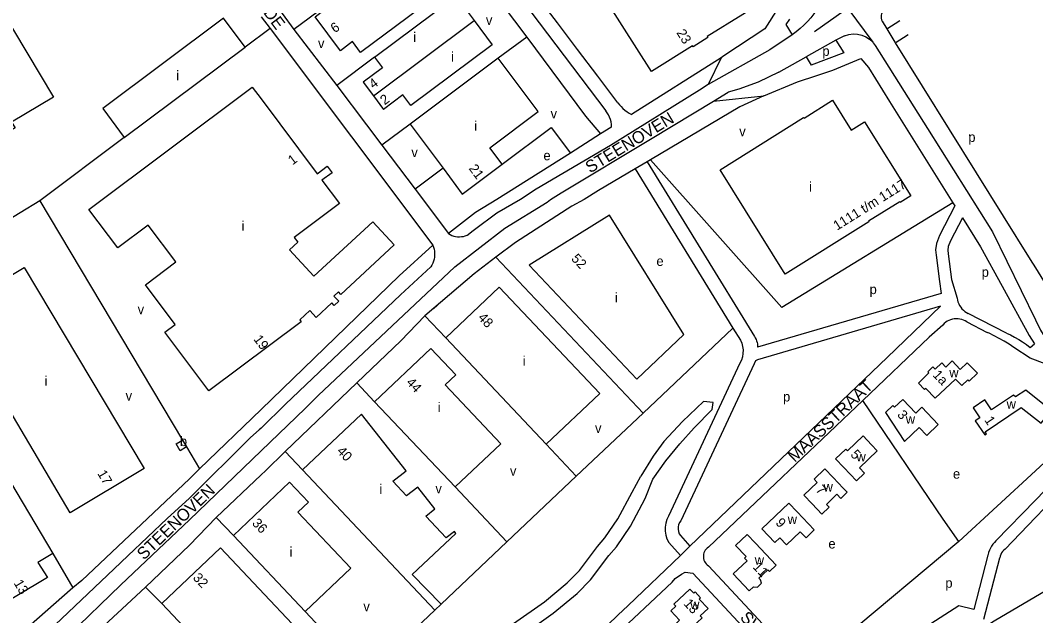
# Model space of a CAD drawing. Extents: x 156721 to 158827, y 386657 to 388950.
# Drawn here: x 157630 to 158050.1, y 388328 to 388574.1 of the extents above; entities that cross this region are included whole.
import ezdxf

# ---------------------------------------------------------------- set-up
doc = ezdxf.new("R2010")
doc.units = 0
for name, color, linetype in [('BLT_Basislijn', 7, 'Continuous'), ('BLT_Bebouwing', 7, 'Continuous'), ('BLT_Centroide', 7, 'Continuous'), ('BLT_Huisnummer', 7, 'Continuous'), ('BLT_Huisnummer_reeks', 7, 'Continuous'), ('BLT_Onderverdeling_panden', 7, 'Continuous'), ('BLT_Straatnaam', 7, 'Continuous'), ('BLT_Vlakafsluiter', 7, 'Continuous')]:
    doc.layers.add(name, color=color, linetype=linetype)

msp = doc.modelspace()

# ---------------------------------------------------------------- linework, layer by layer
at = {"layer": 'BLT_Basislijn'}
for p, q in [((157729.65, 388588.92), (157743.2, 388570.34)), ((157756.41, 388580.15), (157743.2, 388570.34)), ((157729.65, 388575.61), (157733.33, 388570.72)), ((157943.56, 388579.24), (157938.08, 388570.62)), ((157970.91, 388578.09), (157958.64, 388569.41)), ((157948.27, 388574.59), (157946.73, 388572.37)), ((157946.73, 388572.37), (157949.36, 388568.15)), ((157986.64, 388573.72), (157988.5, 388570.64)), ((157988.5, 388570.64), (157993.92, 388574.08)), ((157733.33, 388570.72), (157723.08, 388563.03)), ((157733.33, 388570.72), (157800.68, 388481.2)), ((157743.2, 388570.34), (157761.02, 388547.23)), ((157839.52, 388567.15), (157827.78, 388558.41)), ((157949.36, 388568.15), (157940.12, 388561.92)), ((157971.04, 388567.72), (157967.45, 388565.88)), ((157988.5, 388570.64), (157991.84, 388565.12)), ((157992, 388564.86), (157997.39, 388568.26)), ((157967.45, 388565.88), (157955.08, 388558.95)), ((157967.45, 388565.88), (157970.66, 388560.71)), ((157983.67, 388563.72), (158005.28, 388529.41)), ((157991.84, 388565.12), (157992, 388564.86)), ((157992, 388564.86), (158047.87, 388475.3)), ((157776.63, 388558.9), (157761.02, 388547.23)), ((157940.12, 388561.92), (157914.59, 388547.57)), ((157943.81, 388552.66), (157955.08, 388558.95)), ((157955.08, 388558.95), (157957.22, 388555.52)), ((157970.66, 388560.71), (157957.22, 388555.52)), ((157919.92, 388558.64), (157882.88, 388535.23)), ((157919.92, 388558.64), (157914.59, 388547.57)), ((157966.24, 388553.56), (157977.83, 388558.37)), ((157977.83, 388558.37), (157980.87, 388554.56)), ((157980.87, 388554.56), (157989.62, 388540.54)), ((157943.81, 388552.66), (157935.31, 388548.5)), ((157951.6, 388548.73), (157959.49, 388551.33)), ((157959.49, 388551.33), (157966.24, 388553.56)), ((157761.02, 388547.23), (157773.25, 388530.97)), ((157935.31, 388548.5), (157927.29, 388545.62)), ((157937.66, 388542.9), (157951.6, 388548.73)), ((157916.83, 388540.74), (157937.66, 388542.9)), ((157927.29, 388545.62), (157922.85, 388544.41)), ((157989.62, 388540.54), (158015.89, 388498.67)), ((157773.25, 388530.97), (157779.65, 388522.46)), ((157791.32, 388531.17), (157779.65, 388522.46)), ((157874.37, 388529.85), (157870.11, 388527.16)), ((157874.67, 388530.04), (157874.37, 388529.85)), ((157673.06, 388525.66), (157638.1, 388499.53)), ((157779.65, 388522.46), (157793.34, 388504.27)), ((157804.94, 388512.94), (157793.34, 388504.27)), ((157889.4, 388515.68), (157884.38, 388512.71)), ((157890.71, 388516.46), (157889.4, 388515.68)), ((157890.71, 388516.46), (157945.1, 388455.4)), ((157793.34, 388504.27), (157807.12, 388485.95)), ((157638.1, 388499.53), (157697.08, 388400.6)), ((158015.89, 388498.67), (157945.1, 388455.4)), ((158016.7, 388497.38), (158010.32, 388485.12)), ((158015.89, 388498.67), (158016.7, 388497.38)), ((158019.79, 388492.48), (158014.86, 388483.01)), ((158019.79, 388492.48), (158027.33, 388480.51)), ((158010.32, 388485.12), (158009.01, 388481.93)), ((157800.68, 388481.2), (157786.7, 388468.5)), ((158009.01, 388481.93), (158008.69, 388479.25)), ((158008.69, 388479.25), (158008.89, 388477.03)), ((158013.9, 388480.66), (158013.72, 388479.17)), ((158013.72, 388479.17), (158013.86, 388477.57)), ((158014.86, 388483.01), (158013.9, 388480.66)), ((158027.33, 388480.51), (158036.28, 388464.18)), ((157826.79, 388476.17), (157887.67, 388411.8)), ((158008.89, 388477.03), (158010.28, 388466.17)), ((158013.86, 388477.57), (158015.21, 388467.02)), ((158047.87, 388475.3), (158050, 388471.85)), ((157786.7, 388468.5), (157729.65, 388413.31)), ((158015.21, 388467.02), (158017.56, 388459.27)), ((158010.28, 388466.17), (158011.03, 388461.21)), ((158036.28, 388464.18), (158047.43, 388443.84)), ((158011.03, 388461.21), (157935.06, 388439.02)), ((157800.99, 388454.87), (157802.57, 388456.33)), ((158010.76, 388455.93), (157935.08, 388433.82)), ((157988.68, 388434.81), (158010.76, 388455.93)), ((157797.44, 388451.9), (157806.01, 388442.84)), ((158037.96, 388444.87), (158022.19, 388452.96)), ((157924.81, 388446.92), (157927.94, 388441.94)), ((158011.66, 388448.17), (158006.07, 388443.14)), ((158021.61, 388449.47), (158030.04, 388445.14)), ((158006.07, 388443.14), (157978.63, 388416.92)), ((158047.43, 388443.84), (158049.65, 388440.39)), ((158047.83, 388434.46), (158041.01, 388438.89)), ((158047.79, 388438.91), (158049.65, 388440.39)), ((157988.68, 388434.81), (157907.08, 388356.74)), ((157934.18, 388433.31), (157933.6, 388432.15)), ((157935.08, 388433.82), (157934.18, 388433.31)), ((158054.07, 388432.16), (158047.83, 388434.46)), ((157927.74, 388432.4), (157898.21, 388369.17)), ((157933.6, 388432.15), (157903.25, 388367.25)), ((157912.61, 388416.54), (157904.05, 388408.36)), ((157916.61, 388416.15), (157912.61, 388416.54)), ((157914.69, 388356.3), (157978.63, 388416.92)), ((157916.22, 388413.23), (157916.61, 388416.15)), ((157729.65, 388413.31), (157704.2, 388388.68)), ((157908.82, 388405.63), (157916.22, 388413.23)), ((157904.05, 388408.36), (157896.26, 388400.08)), ((157902.88, 388399.11), (157908.82, 388405.63)), ((157896.26, 388400.08), (157891.78, 388393.95)), ((157897.13, 388392.1), (157902.88, 388399.11)), ((157698.78, 388397.76), (157704.2, 388388.68)), ((157746.83, 388388.26), (157739.66, 388395.84)), ((157847.61, 388398.86), (157860.06, 388385.69)), ((157891.78, 388393.95), (157886.81, 388385.74)), ((157891.76, 388384.48), (157897.13, 388392.1)), ((157729.65, 388386.26), (157731.4, 388387.92)), ((158018.35, 388358.76), (158050, 388387.9)), ((158053.89, 388379.75), (158050, 388375.75)), ((158050, 388375.75), (158033.66, 388358.95)), ((158050, 388368.56), (158057.52, 388376.31)), ((157711.07, 388368.58), (157718.17, 388361.13)), ((158037.41, 388355.59), (158050, 388368.56)), ((157898.28, 388358.34), (157903.11, 388352.94)), ((157903.15, 388361.15), (157907.08, 388356.74)), ((158018.35, 388358.76), (157954.86, 388305.75)), ((158050, 388335.95), (158090.42, 388359.89)), ((157643.55, 388353.78), (157651.82, 388339.53)), ((157903.11, 388352.94), (157881.5, 388332.26)), ((157907.08, 388356.74), (157903.11, 388352.94)), ((158030.32, 388353.03), (158024.57, 388330.64)), ((157954.86, 388305.75), (157914.69, 388348.69)), ((158028.62, 388326.61), (158035.21, 388351.98)), ((157899.76, 388341.9), (157854.79, 388299.87)), ((157651.82, 388339.54), (157630.02, 388320.43)), ((157653.95, 388314.01), (157681.86, 388339.8)), ((157681.86, 388339.8), (157688.52, 388333.06)), ((157877.17, 388328.3), (157881.5, 388332.26)), ((157747.91, 388329.81), (157772.88, 388303.23))]:
    msp.add_line(p, q, dxfattribs=at)
for points in [[(157817.1, 388609.55), (157872.27, 388536.72)], [(157877.21, 388540.06), (157868.9, 388551.04), (157860.59, 388562.02), (157852.28, 388573), (157843.97, 388583.98), (157836.41, 388593.96)], [(157820.95, 388592), (157834.44, 388573.94)], [(157986.64, 388573.72), (157986.45, 388574.32), (157986.33, 388574.94), (157986.3, 388575.57), (157986.34, 388576.19), (157986.46, 388576.81), (157986.67, 388577.41), (157986.94, 388577.97), (157987.29, 388578.5), (157987.69, 388578.98), (157988.16, 388579.41), (157988.67, 388579.77), (157989.23, 388580.06), (157989.82, 388580.28), (157990.17, 388580.36)], [(157959.58, 388578.52), (157958.38, 388576.82), (157957.09, 388575.17), (157955.7, 388573.6), (157954.23, 388572.1), (157952.67, 388570.69), (157951.05, 388569.37), (157949.36, 388568.15)], [(157834.44, 388573.94), (157839.52, 388567.15)], [(157839.52, 388567.15), (157863.9, 388534.53), (157870.11, 388527.16)], [(157938.08, 388570.62), (157921.11, 388559.39), (157919.92, 388558.64)], [(157971.04, 388567.72), (157972.77, 388568.26), (157974.57, 388568.48), (157976.39, 388568.39), (157978.16, 388567.98), (157979.83, 388567.27), (157981.35, 388566.28), (157982.69, 388565.04)], [(157982.69, 388565.04), (157982.84, 388564.84), (157983.67, 388563.72)], [(157914.59, 388547.57), (157911.04, 388545.25), (157874.26, 388522.3), (157843.47, 388504.3), (157836.99, 388500), (157827.16, 388494.34), (157817.87, 388487.54), (157815.63, 388485.69)], [(157937.66, 388542.9), (157927.74, 388538.36), (157890.71, 388516.46)], [(157916.83, 388540.74), (157922.85, 388544.41)], [(157729.65, 388396.17), (157747.83, 388413.66), (157753.23, 388419.1), (157809.77, 388472.21), (157830.48, 388488.25), (157848.04, 388498.95), (157849.35, 388500), (157853.76, 388502.87), (157891.5, 388525.33), (157916.83, 388540.74)], [(157877.21, 388540.06), (157877.87, 388539.22), (157878.59, 388538.42), (157879.36, 388537.67), (157880.18, 388536.97), (157881.04, 388536.33), (157881.95, 388535.75), (157882.88, 388535.23)], [(157874.67, 388530.04), (157874.61, 388531.06), (157874.44, 388532.08), (157874.19, 388533.08), (157873.83, 388534.06), (157873.39, 388535), (157872.87, 388535.89), (157872.27, 388536.72)], [(157829.35, 388514.62), (157849.7, 388529.83), (157857.6, 388519.25)], [(158005.28, 388529.41), (158032.2, 388486.66), (158050, 388450.29)], [(157870.11, 388527.16), (157857.6, 388519.25)], [(157857.6, 388519.25), (157827.14, 388500), (157818.29, 388494.74), (157807.12, 388485.95)], [(157884.38, 388512.71), (157869.2, 388503.73), (157863.36, 388500), (157858.2, 388497.36), (157834.9, 388482.32), (157826.79, 388476.17)], [(157884.38, 388512.71), (157924.81, 388446.92)], [(157889.4, 388515.68), (157933.73, 388443.38)], [(157638.1, 388499.53), (157621.78, 388489.64)], [(157807.12, 388485.95), (157807.82, 388485.55), (157808.56, 388485.21), (157809.33, 388484.95), (157810.12, 388484.77), (157810.93, 388484.66), (157811.74, 388484.64), (157812.55, 388484.69), (157813.36, 388484.82), (157814.14, 388485.04), (157814.9, 388485.33), (157815.63, 388485.69)], [(157800.68, 388481.2), (157800.99, 388480.4), (157801.22, 388479.58), (157801.38, 388478.73), (157801.45, 388477.88), (157801.45, 388477.02), (157801.37, 388476.17), (157801.21, 388475.32), (157800.96, 388474.5), (157800.65, 388473.7), (157800.26, 388472.94), (157799.8, 388472.21)], [(157826.79, 388476.17), (157817.81, 388469.38), (157797.44, 388451.9)], [(157799.8, 388472.21), (157787.37, 388460.64), (157739.75, 388415.46), (157729.65, 388405.55)], [(158050, 388471.85), (158097.61, 388394.52)], [(158017.56, 388459.27), (158017.72, 388458.47), (158017.95, 388457.69), (158018.26, 388456.93), (158018.64, 388456.21), (158019.08, 388455.53), (158019.6, 388454.9), (158020.17, 388454.32), (158020.8, 388453.8), (158021.47, 388453.35), (158022.19, 388452.96)], [(157769.26, 388424.21), (157787.43, 388441.62), (157797.44, 388451.9)], [(158021.61, 388449.47), (158020.94, 388449.87), (158020.24, 388450.2), (158019.51, 388450.46), (158018.75, 388450.64), (158017.98, 388450.75), (158017.2, 388450.77), (158016.43, 388450.71), (158015.66, 388450.58), (158014.92, 388450.36), (158014.19, 388450.07), (158013.51, 388449.71), (158012.86, 388449.28), (158012.26, 388448.79), (158011.66, 388448.17)], [(158050, 388450.29), (158052.1, 388446.01), (158068.65, 388419.47)], [(157924.81, 388446.92), (157887.67, 388411.8)], [(157927.94, 388441.94), (157928.48, 388440.67), (157928.86, 388439.3), (157929.04, 388437.87), (157929.01, 388436.42), (157928.77, 388435), (157928.34, 388433.65), (157927.74, 388432.4)], [(157933.73, 388443.38), (157934.09, 388442.84), (157934.4, 388442.25), (157934.66, 388441.63), (157934.85, 388440.99), (157934.99, 388440.34), (157935.05, 388439.68), (157935.06, 388439.02)], [(158041.01, 388438.89), (158039.07, 388440.2), (158037.08, 388441.45), (158035.05, 388442.62), (158032.99, 388443.72), (158030.88, 388444.75), (158030.04, 388445.14)], [(158037.96, 388444.87), (158039.7, 388444.05), (158041.4, 388443.16), (158043.06, 388442.2), (158044.68, 388441.17), (158046.26, 388440.07), (158047.79, 388438.91)], [(157739.66, 388395.84), (157769.26, 388424.21)], [(157776.62, 388416.43), (157769.26, 388424.21)], [(158018.35, 388358.76), (158011.77, 388367.95), (157978.63, 388416.92)], [(157887.67, 388411.8), (157860.06, 388385.69)], [(157729.65, 388405.55), (157728.9, 388404.8), (157725.22, 388401.64), (157700, 388376.67), (157690.85, 388368.16), (157674.58, 388352.73), (157668.88, 388347.46)], [(158050, 388387.9), (158063.02, 388399.89), (158070.12, 388406.85)], [(157671.64, 388340.75), (157700, 388367.64), (157729.65, 388396.17)], [(157731.4, 388387.92), (157739.66, 388395.84)], [(157704.2, 388388.68), (157700, 388384.62), (157655.46, 388342.57), (157651.82, 388339.54)], [(157711.07, 388368.58), (157729.65, 388386.26)], [(157860.06, 388385.69), (157831.37, 388358.55)], [(157834.06, 388324.76), (157846.86, 388333.8), (157856.31, 388341.64), (157861.35, 388346.73), (157868.85, 388356.62), (157871.83, 388360.15), (157877.28, 388368.11), (157883.15, 388379.15), (157886.81, 388385.74)], [(157837.38, 388319.76), (157850.51, 388329.04), (157860.37, 388337.21), (157865.9, 388342.79), (157873.53, 388352.87), (157876.61, 388356.51), (157882.43, 388365), (157888.53, 388376.5), (157891.76, 388384.48)], [(157831.37, 388358.55), (157809.88, 388381.27)], [(157711.07, 388368.58), (157700, 388357.18), (157681.86, 388339.8)], [(157898.21, 388369.17), (157897.51, 388367.76), (157897.02, 388366.22), (157896.76, 388364.58), (157896.77, 388362.91), (157897.04, 388361.28), (157897.56, 388359.74), (157898.28, 388358.34)], [(157903.25, 388367.25), (157902.75, 388366.51), (157902.38, 388365.65), (157902.17, 388364.7), (157902.16, 388363.73), (157902.33, 388362.78), (157902.67, 388361.91), (157903.15, 388361.15)], [(157804.16, 388332.81), (157831.37, 388358.55)], [(158033.66, 388358.95), (158033, 388358.28), (158032.39, 388357.54), (158031.85, 388356.76), (158031.37, 388355.94), (158030.96, 388355.08), (158030.63, 388354.19), (158030.38, 388353.27), (158030.32, 388353.03)], [(157914.69, 388356.3), (157914.2, 388355.95), (157913.77, 388355.53), (157913.4, 388355.06), (157913.09, 388354.54), (157912.86, 388353.99), (157912.7, 388353.41), (157912.62, 388352.81), (157912.62, 388352.21), (157912.69, 388351.61), (157912.85, 388351.03), (157913.08, 388350.48), (157913.39, 388349.96), (157913.75, 388349.49), (157914.18, 388349.06), (157914.69, 388348.69)], [(158037.41, 388355.59), (158036.88, 388355.11), (158036.41, 388354.57), (158036.01, 388353.99), (158035.67, 388353.36), (158035.41, 388352.7), (158035.21, 388351.98)], [(157552.85, 388284.58), (157562.27, 388288.83), (157576.98, 388292.83), (157591.14, 388294.71), (157604.51, 388297.91), (157617.07, 388303.26), (157630.17, 388311.28), (157641.66, 388321.7), (157668.88, 388347.46)], [(157899.76, 388341.9), (157900.99, 388343.34), (157903.52, 388345.24), (157905.15, 388346.05), (157908.19, 388345.66), (157930.77, 388321.49)], [(157671.64, 388340.75), (157649.95, 388319.83), (157637.38, 388308.07), (157628.83, 388301.66), (157619.74, 388296.31), (157610.65, 388292.57), (157599.96, 388289.36), (157589.27, 388286.69), (157580.99, 388285.88), (157567.89, 388281.34), (157559.87, 388277.87), (157552.39, 388274.39), (157548.51, 388271.92)], [(158024.57, 388330.64), (158018.33, 388332.1), (157989.39, 388313.55), (157988.64, 388310.72)], [(158027.05, 388322.01), (158032.97, 388325.86), (158050, 388335.95)], [(157801.58, 388330.37), (157772.88, 388303.23)], [(157807.52, 388263.23), (157868.91, 388320.31), (157877.17, 388328.3)]]:
    msp.add_lwpolyline(points, dxfattribs=at)
at = {"layer": 'BLT_Bebouwing'}
for p, q in [((157776.63, 388558.9), (157810.28, 388584.04)), ((157799.87, 388438.42), (157776.62, 388416.43)), ((157810.18, 388427.52), (157799.87, 388438.42)), ((157805.82, 388423.4), (157810.18, 388427.52)), ((157828.77, 388399.13), (157805.82, 388423.4)), ((157776.62, 388416.43), (157809.88, 388381.27)), ((157697.08, 388400.6), (157698.78, 388397.76)), ((157809.88, 388381.27), (157828.77, 388399.13)), ((157718.17, 388361.13), (157747.91, 388329.81)), ((157801.58, 388330.37), (157804.16, 388332.81))]:
    msp.add_line(p, q, dxfattribs=at)
for points in [[(157943.66, 388585.67), (157914.19, 388567.45), (157914.49, 388566.97), (157908.34, 388563.13), (157908.08, 388563.55), (157891.16, 388552.94), (157865.87, 388592.62), (157902.5, 388615.47)], [(157795.49, 388609.35), (157809.91, 388590.06), (157770.83, 388560.86), (157767.51, 388565.34)], [(157617.92, 388606.99), (157631.09, 388584.92), (157632.51, 388582.55), (157627.01, 388579.27), (157625.55, 388581.71), (157621.73, 388579.33), (157643.79, 388542.4), (157626.43, 388532.05), (157627.89, 388529.61), (157605.78, 388516.39)], [(157810.28, 388584.04), (157817.77, 388574.01)], [(157767.51, 388565.34), (157762.43, 388561.54), (157751.95, 388575.56), (157757.01, 388579.34)], [(157723.08, 388563.03), (157714.16, 388574.98), (157664.15, 388537.62), (157673.06, 388525.66)], [(157817.77, 388574.01), (157825.26, 388563.99), (157791.61, 388538.85), (157788.3, 388543.26), (157780.32, 388537.28)], [(157673.06, 388525.66), (157723.08, 388563.03)], [(157776.63, 388558.9), (157779.93, 388554.48), (157771.94, 388548.5), (157776.13, 388542.88)], [(157827.78, 388558.41), (157791.32, 388531.17)], [(157829.35, 388514.62), (157824.27, 388521.42), (157844.26, 388536.36), (157827.78, 388558.41)], [(157707.99, 388420.9), (157689.84, 388445.18), (157694.11, 388448.37), (157681.82, 388464.77), (157694.42, 388474.22), (157682.96, 388489.5), (157670.36, 388480.06), (157658.43, 388495.98), (157726.02, 388546.53), (157729.65, 388541.67)], [(157776.13, 388542.88), (157780.32, 388537.28)], [(157729.65, 388541.67), (157752.81, 388510.69), (157757.04, 388513.82), (157759.03, 388511.13), (157754.83, 388507.99), (157762.02, 388498.37), (157743.32, 388484.39), (157744.83, 388482.37), (157741.36, 388479.24), (157751.47, 388468.31), (157775.82, 388490.83), (157784.71, 388481.25), (157762.61, 388460.81), (157761.6, 388461.83), (157759.8, 388460.16), (157761.79, 388457.97), (157759.9, 388456.21), (157758.85, 388457.33), (157752.37, 388451.31), (157749.74, 388454.11), (157745.62, 388450.3), (157746.2, 388449.49), (157707.99, 388420.9)], [(157791.32, 388531.17), (157804.94, 388512.94)], [(157804.94, 388512.94), (157812.88, 388502.31), (157829.35, 388514.62)], [(157650.6, 388370.54), (157616.7, 388427.68), (157614.49, 388426.12), (157598.9, 388452.58), (157631.64, 388472.01)], [(157631.64, 388472.01), (157681.27, 388388.86), (157650.6, 388370.54)], [(157847.61, 388398.86), (157869.79, 388419.85), (157828.19, 388463.83), (157806.01, 388442.84)], [(157806.01, 388442.84), (157847.61, 388398.86)], [(158008.5, 388417.89), (158004.61, 388421.99), (158004.13, 388421.54), (158001.6, 388424.2), (158005.96, 388428.34), (158005.46, 388428.87), (158007.59, 388430.9), (158008.56, 388429.88), (158011.34, 388432.5), (158012.96, 388430.78), (158015.58, 388433.3), (158018.83, 388429.76)], [(158018.83, 388429.76), (158021.82, 388432.6), (158025.98, 388428.24), (158022.58, 388425), (158022.06, 388425.55), (158019.56, 388423.15), (158016.98, 388425.83), (158008.5, 388417.89)], [(157608.76, 388412.02), (157643.55, 388353.78)], [(157804.16, 388332.81), (157792.21, 388345.11), (157810.18, 388362.06), (157809.59, 388362.81), (157806.23, 388360.18), (157797.75, 388369.2), (157801.58, 388372.22), (157794.5, 388381.2), (157789.84, 388377.52), (157784.09, 388383.59), (157789.61, 388387.96), (157771.2, 388411.31), (157746.83, 388388.26)], [(157698.78, 388397.76), (157696.21, 388396.22), (157694.5, 388399.04), (157697.08, 388400.6)], [(157982.15, 388398.7), (157984.57, 388396.17), (157977.17, 388389.16), (157979.33, 388386.89), (157976.03, 388383.73), (157970.75, 388389.24), (157967.29, 388392.85), (157971.57, 388396.91), (157972.23, 388396.18), (157978.7, 388402.31), (157982.15, 388398.7)], [(157746.83, 388388.26), (157801.58, 388330.37)], [(157966.38, 388385.09), (157962.92, 388388.69), (157958.46, 388384.41), (157959.68, 388383.14), (157954.13, 388377.81), (157957.59, 388374.2), (157961.66, 388369.97), (157964.65, 388372.84), (157963.5, 388374.04), (157967.85, 388378.22), (157969.51, 388376.49), (157972.17, 388379.05), (157970.52, 388380.78), (157966.38, 388385.09)], [(157747.91, 388329.81), (157766.76, 388347.72), (157744.83, 388370.8), (157749.21, 388374.95), (157741.41, 388383.16), (157718.17, 388361.13)], [(157951.41, 388370.9), (157956.11, 388365.97), (157958.48, 388363.47), (157955.09, 388360.25), (157952.71, 388362.75), (157947.04, 388357.36), (157944.28, 388360.26), (157942.17, 388358.26), (157936.8, 388363.91), (157947.96, 388374.53), (157951.41, 388370.9)], [(157936.63, 388341.42), (157936.32, 388342.81), (157935.62, 388343.55), (157939.23, 388346.98), (157939.93, 388346.24), (157942.76, 388348.93), (157934.18, 388357.95), (157930.74, 388361.57), (157925.96, 388357.03), (157930.3, 388352.47), (157929.65, 388351.85), (157930.69, 388350.76), (157924.96, 388345.31), (157931.62, 388338.31), (157933.32, 388339.93), (157935.02, 388339.88), (157936.63, 388341.42)], [(157643.55, 388353.78), (157637.34, 388350.08), (157641.29, 388343.79), (157615.8, 388328.62)], [(157736.41, 388282.4), (157760.72, 388305.4), (157712.82, 388356.05), (157688.52, 388333.06)], [(157688.52, 388333.06), (157736.41, 388282.4)]]:
    msp.add_lwpolyline(points, dxfattribs=at)
for points in [[(157919.5, 388512.34), (157954.1, 388533.97), (157954.3, 388533.68), (157966.07, 388541.04), (157973.75, 388528.74), (157979.26, 388532.17), (157998.41, 388501.51), (157994.09, 388498.79), (157993.89, 388499.13), (157980.91, 388491.06), (157981.09, 388490.76), (157946.51, 388469.14)], [(157840.59, 388472.91), (157885.14, 388425.81), (157904.58, 388444.25), (157873.82, 388493.63)], [(158056.56, 388412.78), (158045.96, 388421.28), (158041.71, 388418.43), (158040.87, 388419.11), (158031.86, 388413.08), (158029.01, 388417.18), (158024.19, 388413.96), (158026.97, 388409.81), (158025.09, 388408.56), (158029, 388402.74), (158029.76, 388403.23), (158029.21, 388404.08), (158044.14, 388414.08), (158052.39, 388407.54)], [(157995.14, 388417.44), (157991.72, 388414.16), (157990.96, 388414.94), (157987.91, 388412.04), (157995.77, 388399.96), (158001.94, 388405.82), (158005.04, 388402.57), (158009.79, 388407.09), (158003.05, 388414.18), (158000.52, 388411.77)], [(157905.54, 388315.74), (157899.13, 388322.62), (157902.75, 388326.21), (157899.17, 388330.01), (157901.26, 388331.97), (157900.44, 388332.86), (157907, 388339.05), (157908.61, 388337.39), (157909.17, 388337.91), (157911.47, 388335.48), (157910.92, 388334.93), (157914.56, 388331.05), (157911.26, 388327.96), (157912.07, 388327.09), (157905.93, 388321.3), (157908.5, 388318.56)]]:
    msp.add_lwpolyline(points, close=True, dxfattribs=at)
at = {"layer": 'BLT_Onderverdeling_panden'}
msp.add_line((157776.13, 388542.88), (157817.77, 388574.01), dxfattribs=at)
at = {"layer": 'BLT_Vlakafsluiter'}
msp.add_line((157972.37, 388579.02), (157982.69, 388565.04), dxfattribs=at)

# ---------------------------------------------------------------- texts
at = {"layer": 'BLT_Centroide'}
for s, p in [('v', (157822.65, 388572.21)), ('i', (157792.61, 388565.19)), ('v', (157753.18, 388562.63)), ('i', (157808.22, 388557.07)), ('p', (157961.86, 388559.42)), ('i', (157694.53, 388549.35)), ('v', (157849.41, 388533.57)), ('i', (157817.8, 388528.45)), ('v', (157927.46, 388526.22)), ('p', (158022.22, 388523.85)), ('v', (157791.81, 388517.57)), ('e', (157846.45, 388516.25)), ('i', (157956.32, 388503.33)), ('i', (157721.56, 388487.12)), ('e', (157893.19, 388472.59)), ('p', (158027.76, 388468.08)), ('p', (157981.39, 388460.94)), ('i', (157875.99, 388457.48)), ('v', (157678.58, 388452.64)), ('i', (157837.91, 388431.34)), ('w', (158014.35, 388426.57)), ('i', (157640.09, 388423.05)), ('v', (157673.61, 388416.95)), ('i', (157802.69, 388412.16)), ('p', (157945.58, 388416.57)), ('w', (158038.07, 388413.56)), ('w', (157996.35, 388407.35)), ('v', (157867.79, 388403.57)), ('b', (157696.06, 388398.14)), ('w', (157975.94, 388391.77)), ('v', (157832.6, 388385.89)), ('e', (158015.88, 388384.67)), ('i', (157778.55, 388378.39)), ('w', (157962.33, 388379.36)), ('v', (157801.76, 388378.61)), ('w', (157947.51, 388365.94)), ('e', (157964.34, 388355.8)), ('i', (157741.45, 388352.45)), ('w', (157933.86, 388349.09)), ('p', (158012.72, 388339.58)), ('v', (157771.95, 388329.87)), ('w', (157907.16, 388330.8))]:
    msp.add_text(s, height=4, dxfattribs=at).set_placement(p)
at = {"layer": 'BLT_Huisnummer'}
for s, rotation, p in [('6', 35.0807, (157760.13, 388568.69)), ('4', 36.7818, (157776.12, 388545.63)), ('2', 36.8223, (157780.77, 388538.95)), ('21', 306.7687, (157815.39, 388512.81)), ('52', 313.4044, (157857.71, 388475.36)), ('48', 313.4044, (157819.09, 388450.99)), ('1a', 313.991, (158007.25, 388427.28)), ('44', 313.4045, (157789.45, 388424.18)), ('3', 309.991, (157992.58, 388410.97)), ('1', 303.991, (158028.74, 388408.86)), ('40', 313.4045, (157760.73, 388395.8)), ('5', 313.7763, (157973.24, 388394.39)), ('17', 300.6037, (157661.77, 388386.83)), ('7', 313.8332, (157958.84, 388379.76)), ('36', 313.4007, (157725.66, 388366.03)), ('9', 313.5657, (157942.24, 388366.18)), ('11', 313.5531, (157932.8, 388347.94)), ('32', 313.4044, (157701.17, 388343.46)), ('13', 300.9891, (157627.16, 388341.52)), ('13', 313.1402, (157904.21, 388332.8))]:
    msp.add_text(s, height=4, rotation=rotation, dxfattribs=at).set_placement(p)
at = {"layer": 'BLT_Huisnummer_reeks'}
for s, rotation, p in [('23', 301.9598, (157901.36, 388568.96)), ('1', 36.7886, (157742.62, 388514.09)), ('1111 t/m 1117', 32.0202, (157967.93, 388487.13)), ('19', 306.7837, (157726.33, 388442.27))]:
    msp.add_text(s, height=4, rotation=rotation, dxfattribs=at).set_placement(p)
at = {"layer": 'BLT_Straatnaam'}
for s, rotation, p in [('BOVEN ZIJDE', 306.9553, (157709.63, 388604.83)), ('STEENOVEN', 31.3397, (157865.75, 388510.76)), ('MAASSTRAAT', 43.6039, (157950.43, 388391.15)), ('STEENOVEN', 43.6862, (157681.18, 388350.79)), ('SWALMSTRAAT', 312.8218, (157927.47, 388327.01))]:
    msp.add_text(s, height=5, rotation=rotation, dxfattribs=at).set_placement(p)

doc.saveas('drawing.dxf')
